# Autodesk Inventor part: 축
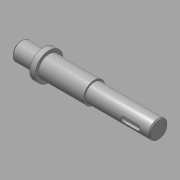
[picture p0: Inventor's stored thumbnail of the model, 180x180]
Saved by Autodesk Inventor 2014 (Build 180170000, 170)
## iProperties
Created: 2015-09
Part Number: 축
Material: 강철, 연강
Document SubType Name: Modeling
Designer: mduedu
Density: 7.86 g/cm^3
Mass: 263.428 g
Surface Area: 86.4309 cm^2
Volume: 33.515 cm^3
Appearance: Steel
Author: mduedu
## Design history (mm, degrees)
sketch "스케치1"
  geometry: L1 (-64, 0)-(64, 0); L2 (-64, 0)-(-64, 8.5); L3 (-64, 8.5)-(-43, 8.5); L4 (-43, 8.5)-(-43, 13); L5 (-43, 13)-(-38, 13); L6 (-38, 13)-(-38, 10); L7 (-38, 10)-(4, 10); L8 (4, 10)-(4, 8.5); L9 (4, 8.5)-(64, 8.5); L10 (64, 8.5)-(64, 0); 2 further points
  constraints: 20 end point, 5 parallel, 2 horizontal, 2 perpendicular, 1 coincident, 1 midpoint, 1 vertical
  dimensions: "d0" = 128 distance of L1.start L1.end; "d2" = 5 distance of L4.end L5.end; "d3" = 42 distance of L6.end L7.end; "d4" = 60 distance of L8.end L9.end; "d5" = 17 diameter of L3 L1; "d6" = 17 diameter of L9 L1; "d7" = 20 diameter of L7 L1; "d8" = 26 diameter of L5 L1
revolve "회전1" sketch "스케치1" stored, may be unused: angle "d9" = 90 deg
node "작업 평면1"
sketch "스케치2"
  geometry: L1 (5.5, 2.5)-(18.5, 2.5); L2 (18.5, -2.5)-(5.5, -2.5); L3 (5.5, 2.5)-(18.5, -2.5); L4 (18.5, 2.5)-(5.5, -2.5); L5 (30, -8.5)-(30, 8.5) reference; A1 r 2.5 centre (5.5, 0) between (5.5, 2.5) and (5.5, -2.5); A2 r 2.5 centre (18.5, 0) between (18.5, -2.5) and (18.5, 2.5); 2 further points
  constraints: 8 end point, 4 point on circle, 4 tangent, 2 centre point, 2 midpoint, 1 horizontal, 1 horizontal alignment, 1 parallel
  dimensions: "d10" = 18 dimension on A2 A1; "d12" = 9 distance edge to line of A2 L5; "d13" = 5 distance between parallel lines of L2 L1
extrude "돌출1" cut sketch "스케치2" distance "d14" = 3; taper "d15" = 0 deg
node "작업 평면2"
sketch "스케치4"
  geometry: L1 (7, -3)-(-9, -3); L2 (-9, 3)-(7, 3); L3 (-21, 10)-(-21, -10) reference; A1 r 3 centre (-9, 0) between (-9, 3) and (-9, -3); A2 r 3 centre (7, 0) between (7, -3) and (7, 3); 1 further point
  constraints: 4 end point, 4 point on circle, 4 tangent, 2 centre point, 1 horizontal, 1 horizontal alignment, 1 parallel
  dimensions: "d16" = 22 dimension on A1 A2; "d18" = 6 distance between parallel lines of L2 L1; "d19" = 9 distance edge to line of A1 L3
extrude "돌출2" cut sketch "스케치4" distance "d20" = 3.5; taper "d21" = 0 deg
sketch "스케치5"
  geometry: L1 (4, 8.5)-(64, 8.5) reference; L2 (4, -8.5)-(64, -8.5) reference; L3 (37, 8.5)-(37, -8.5); L4 (37, -6.5)-(35, -8.5); L5 (37, -8.5)-(35, -8.5); L6 (37, -8.5)-(37, -6.5); L7 (4, -10)-(4, 10) reference; 1 further point
  constraints: 8 end point, 4 point on line, 1 collinear, 1 perpendicular
  dimensions: "d22" = 4 diameter of L4.end L3; "d24" = 45 deg angle of L3 L4; "d26" = 33 distance between parallel lines of L3 L7
revolve "회전2" sketch "스케치5" stored, may be unused: angle "d27" = 90 deg
chamfer "모따기1" distance "d28" = 1; stored, may be unused: second distance "d29" = 2, angle "d30" = 45 deg
sketch "스케치6"
  geometry: L1 (37, -6.5)-(35, -8.5) reference; L2 (37, -6.5)-(39, -8.5) reference; 2 further points
  constraints: 1 coincident
node "솔리드1"
